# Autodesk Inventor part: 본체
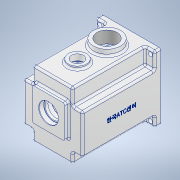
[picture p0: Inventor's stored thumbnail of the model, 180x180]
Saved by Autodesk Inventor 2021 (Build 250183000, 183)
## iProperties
Created: 2022-08
Part Number: 본체
Material: 알루미늄 6061
Document SubType Name: Modeling
Designer: Owner
Mass: 1399.43 g
Surface Area: 1169.88 cm^2
Volume: 518.309 cm^3
Density: 2.7 g/cm^3
Appearance: 알루미늄 - 평지
Author: Owner
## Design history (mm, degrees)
sketch "스케치1"
  geometry: L1 (-49, 55)-(49, 55); L2 (49, 55)-(49, -55); L3 (49, -55)-(-49, -55); L4 (-49, -55)-(-49, 55); L5 (-49, 55)-(49, -55); L6 (49, 55)-(-49, -55); 3 further points
  constraints: 12 end point, 3 midpoint, 2 parallel, 1 coincident, 1 horizontal, 1 perpendicular
  dimensions: "d0" = 98 distance of L2.end L3.end; "d1" = 110 distance of L1.end L2.end
extrude "돌출1" new body sketch "스케치1" stored distance "d2" = 130; taper "d3" = 0 deg
sketch "스케치4"
  geometry: L1 (49, 55)-(-49, 55) reference; L2 (49, 55)-(33, 55); L3 (33, 55)-(33, 28); L4 (33, 28)-(49, 28); L5 (49, 28)-(49, 55); L6 (-49, 55)-(-33, 55); L7 (-33, 55)-(-33, 28); L8 (-33, 28)-(-49, 28); L9 (-49, 28)-(-49, 55); L10 (-49, -55)-(-33, -55); L11 (-33, -55)-(-33, -38); L12 (-33, -38)-(-49, -38); L13 (-49, -38)-(-49, -55); L14 (49, -55)-(33, -55); L15 (33, -55)-(33, -38); L16 (33, -38)-(49, -38); L17 (49, -38)-(49, -55); 4 further points
  constraints: 32 end point, 8 parallel, 4 horizontal, 4 perpendicular, 1 coincident
  dimensions: "d6" = 16 distance of L3.end L4.end; "d7" = 16 distance of L7.end L8.end; "d8" = 27 distance of L2.end L3.end; "d9" = 27 distance of L6.end L7.end; "d10" = 17 distance of L10.end L11.end; "d11" = 16 distance of L11.end L12.end; "d12" = 16 distance of L15.end L16.end; "d13" = 17 distance of L14.end L15.end
extrude "돌출2" cut sketch "스케치4" distance "d14" = 120; taper "d15" = 0 deg
sketch "스케치5"
  geometry: L1 (33, 55)-(-33, 55) reference; L2 (-27, 33)-(27, 33); L3 (27, 33)-(27, -21); L4 (27, -21)-(-27, -21); L5 (-27, -21)-(-27, 33); L6 (-27, 33)-(27, -21); L7 (27, 33)-(-27, -21); L8 (-33, -55)-(33, -55) reference; 3 further points
  constraints: 12 end point, 3 midpoint, 2 parallel, 1 horizontal, 1 perpendicular, 1 vertical alignment
  dimensions: "d146" = 54 distance of L2.start L2.end; "d147" = 54 distance of L2.end L3.end; "d148" = 61 distance from line of L8 point (0, 6)
extrude "돌출3" join sketch "스케치5" distance "d19" = 7; taper "d20" = 0 deg
sketch "스케치6"
  geometry: L1 (-33, -55)-(33, -55) reference; 2 further points
  constraints: 1 vertical alignment
  dimensions: "d151" = 61 distance from line of L1 point (0, 6)
sketch "스케치7"
  geometry: L1 (-23, 45)-(23, 45); L2 (23, 45)-(23, 30.143); L3 (23, 10.468)-(-23, 10.468); L4 (-23, 30.143)-(-23, 45); L5 (-49, -55)-(49, -55) reference; L6 (-36, 4)-(-41.809, 4); L7 (-36, -4)-(-41.809, -4); L8 (36, 4)-(41.809, 4); L9 (36, -4)-(41.809, -4); A1 r 4 centre (-36, 0) between (-36, -4) and (-36, 4); A2 r 4 centre (36, 0) between (36, 4) and (36, -4); A3 r 42 centre (0, -5) between (-23, 30.143) and (23, 30.143); 2 further points
  constraints: 16 end point, 6 point on circle, 5 horizontal, 4 tangent, 3 centre point, 2 horizontal alignment, 2 parallel, 2 vertical alignment, 1 midpoint, 1 perpendicular
  dimensions: "d22" = 46 distance of L3.start L3.end; "d23" = 100 distance between parallel lines of L5 L1; "d26" = 8 diameter of A1; "d27" = 36 distance of point (0, 0) A1.centre; "d28" = 8 diameter of A2; "d29" = 36 distance of A2.centre point (0, 0); "d30" = 46 distance of L1.start L1.end; "d189" = 84 diameter of A3; "d190" = 50 distance from line of A3.centre L5
extrude "돌출4" cut sketch "스케치7" distance "d24" = 121; taper "d25" = 0 deg
sketch "스케치8"
  geometry: L1 (-49, -55)-(49, -55) reference; C1 r 21 at (0, 6); 1 further point
  constraints: 1 centre point, 1 vertical alignment
  dimensions: "d149" = 42 diameter of C1; "d150" = 61 distance from line of L1 C1.centre
extrude "돌출5" join sketch "스케치8" distance "d33" = 7; taper "d34" = 0 deg
sketch "스케치9"
  geometry: L1 (-26, 48)-(26, 48); L2 (26, 48)-(26, 31.729); L3 (-26, 31.729)-(-26, 48); L4 (-49, -55)-(49, -55) reference; A1 r 45 centre (0, -5) between (-26, 31.729) and (26, 31.729); 3 further points
  constraints: 6 end point, 2 point on circle, 2 vertical alignment, 1 centre point, 1 horizontal, 1 midpoint, 1 parallel, 1 perpendicular, 1 point on line
  dimensions: "d36" = 52 distance of L1.start L1.end; "d37" = 103 distance from line of L4 point (0, 48); "d187" = 90 diameter of A1; "d188" = 50 distance from line of A1.centre L4
extrude "돌출6" cut sketch "스케치9" distance "d38" = 9; taper "d39" = 0 deg
hole "구멍1" sketch "스케치6" diameter "d40" = 28; stored, may be unused: countersink angle "d44" = 90 deg, drill point angle "d46" = 0 deg; dims "d41" = 6, "d42" = 32, "d43" = 8.3, "d45" = 100000
chamfer "모따기1" distance "d54" = 0.8; stored, may be unused: second distance "d55" = 2, angle "d56" = 30 deg
fillet "모깎기1" dims "d57" = 0.3
sketch "스케치13"
  geometry: L1 (-49, -55)-(49, -55) reference; A1 r 15 centre (0, -25) between (-8.978, -12.984) and (8.978, -12.984); A2 r 21 centre (0, 6) between (8.978, -12.984) and (-8.978, -12.984) reference; 3 further points
  constraints: 4 point on circle, 1 centre point, 1 vertical alignment
  dimensions: "d153" = 30 diameter of A1; "d169" = 30 distance from line of L1 A1.centre
extrude "돌출7" join sketch "스케치13" distance "d80" = 7; taper "d81" = 0 deg
sketch "스케치16"
  geometry: L1 (0, 0)-(98, 0) reference; C1 r 15 at (49, -89); 1 further point
  constraints: 1 centre point, 1 vertical alignment
  dimensions: "d93" = 30 diameter of C1; "d94" = 89 distance from line of L1 C1.centre
extrude "돌출9" join sketch "스케치16" distance "d95" = 5; taper "d96" = 0 deg
sketch "스케치17"
  geometry: L1 (0, 0)-(98, 0) reference; C1 r 22.5 at (49, -40); 1 further point
  constraints: 1 centre point, 1 vertical alignment
  dimensions: "d97" = 45 diameter of C1; "d98" = 40 distance from line of L1 C1.centre
extrude "돌출10" join sketch "스케치17" distance "d99" = 10; taper "d100" = 0 deg
sketch "스케치18"
  geometry: C1 r 15 at (23, -32) reference; 2 further points
  constraints: 1 coincident
hole "구멍6" sketch "스케치18" at (23, -32) diameter "d101" = 20; stored, may be unused: countersink angle "d105" = 90 deg, drill point angle "d107" = 0 deg; dims "d102" = 7, "d103" = 30, "d104" = 5, "d106" = 7
fillet "모깎기3" dims "d115" = 3
sketch "스케치20"
  geometry: L1 (46, 55)-(-46, 55) reference; L2 (49, -52)-(49, 52) reference; 2 further points
  dimensions: "d116" = 7 distance from line of L1 point (42, 48); "d117" = 7 distance from line of L2 point (42, 48)
hole "구멍8" sketch "스케치20" at (42, 48) diameter "d118" = 7; stored, may be unused: countersink angle "d122" = 90 deg, drill point angle "d124" = 0 deg; dims "d119" = 70, "d120" = 30, "d121" = 5, "d123" = 77.3
fillet "모깎기4" dims "d125" = 3
fillet "모깎기5" dims "d126" = 3
fillet "모깎기6" dims "d127" = 3
fillet "모깎기7" dims "d128" = 3
fillet "모깎기9" dims "d130" = 3
fillet "모깎기10" dims "d131" = 3
fillet "모깎기11" dims "d135" = 3
chamfer "모따기4" distance "d139" = 1; stored, may be unused: second distance "d140" = 2, angle "d141" = 30 deg
sketch "스케치21"
  geometry: L1 (-130, 104)-(-130, 83) reference; L2 (-13, 107)-(-127, 107) reference; 2 further points
  constraints: 1 other
  dimensions: "d142" = 65 distance from line of L1 point (-65, 47); "d143" = 60 distance from line of point (-65, 47) L2
feature "엠보싱1" sketch "스케치21" dims "d144" = 0.5, "d145" = 0
sketch "스케치22"
  geometry: A1 r 21 centre (0, 6) between (8.978, -12.984) and (-8.978, -12.984) reference; 2 further points
  constraints: 1 coincident
hole "구멍9" sketch "스케치22" at (0, 6) diameter "d155" = 35; stored, may be unused: countersink angle "d159" = 90 deg, drill point angle "d161" = 0 deg; dims "d156" = 70, "d157" = 30, "d158" = 5, "d160" = 10
sketch "스케치23"
  geometry: A1 r 15 centre (0, -25) between (-8.978, -12.984) and (8.978, -12.984) reference; 2 further points
  constraints: 1 coincident
hole "구멍10" sketch "스케치23" at (0, -25) diameter "d162" = 22; stored, may be unused: countersink angle "d166" = 90 deg, drill point angle "d168" = 0 deg; dims "d163" = 70, "d164" = 30, "d165" = 5, "d167" = 7
chamfer "모따기5" distance "d170" = 1; stored, may be unused: second distance "d171" = 2, angle "d172" = 30 deg
fillet "모깎기12" dims "d173" = 3
fillet "모깎기13" dims "d174" = 3
sketch "스케치24"
  geometry: C1 r 9.5 at (0, 0); C2 r 11 at (0, 0) reference; 1 further point
  constraints: 1 centre point, 1 concentric
  dimensions: "d175" = 19 diameter of C1
extrude "돌출11" cut sketch "스케치24" distance "d176" = 3; taper "d177" = 0 deg
fillet "모깎기14" dims "d178" = 3
fillet "모깎기15" dims "d179" = 3
sketch "스케치26"
  geometry: L1 (-46, -55)-(46, -55) reference; L2 (-36, -1)-(-41.809, -1); L3 (-36, -9)-(-41.809, -9); A1 r 4 centre (-36, -5) between (-36, -9) and (-36, -1); A2 r 42 centre (0, -5) between (-23, 30.143) and (23, 30.143) reference; 1 further point
  constraints: 4 end point, 4 point on circle, 2 horizontal, 2 tangent, 1 centre point
  dimensions: "d191" = 8 diameter of A1; "d192" = 50 distance from line of L1 A1.centre; "d193" = 36 horizontal distance of point (0, 0) A1.centre
extrude "돌출12" join sketch "스케치26" distance "d194" = 121; taper "d195" = 0 deg
sketch "스케치27"
  geometry: A1 r 4 centre (-36, -5) between (-36, -9) and (-36, -1) reference; 2 further points
  constraints: 1 coincident
hole "구멍12" sketch "스케치27" at (-36, -5) diameter "d196" = 3.242; stored, may be unused: countersink angle "d200" = 90 deg, drill point angle "d202" = 118 deg; dims "d197" = 7, "d198" = 30, "d199" = 5, "d201" = 9
fillet "모깎기16" dims "d203" = 3
fillet "모깎기17" dims "d204" = 3
fillet "모깎기18" dims "d205" = 3
chamfer "모따기6" distance "d206" = 1; stored, may be unused: second distance "d207" = 2, angle "d208" = 30 deg
sketch "스케치28"
  geometry: C1 r 22.5 at (0, 0) reference; 2 further points
  constraints: 1 coincident
hole "구멍13" sketch "스케치28" at (0, 0) diameter "d209" = 33.376; stored, may be unused: countersink angle "d213" = 90 deg, drill point angle "d215" = 0 deg; dims "d210" = 70, "d211" = 30, "d212" = 5, "d214" = 77.3
fillet "모깎기19" dims "d216" = 0.3
fillet "모깎기20" dims "d217" = 3
node "솔리드1"
mirror "미러2"
mirror "미러3"
mirror "미러4"
feature "A9D066F2-1C7D-4E18-AEED-F7BC21143FA4" dims "d40" = 28, "d41" = 6, "d42" = 32, "d43" = 8.3, "d44" = 90 deg, "d45" = 100000, "d46" = 0
